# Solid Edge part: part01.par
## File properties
Author: Robert a Rhodes jr
Template: normal.par
Last saved by: Cadcim
Revision: 14
Application: Solid Edge
Accuracy: 0.99
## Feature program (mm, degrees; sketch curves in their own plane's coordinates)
sketch for "unnamed Protrusion 1" plane through (0, 0, 0) normal (0, 0, 1) x-axis (1, 0, 0)
  line (-63.0032, 49) -> (-56, -71)
  line (-56, -71) -> (56, -71)
  line (56, -71) -> (63.0032, 49)
  line (63.0032, 49) -> (0, 54)
  line (0, 54) -> (-63.0032, 49)
  dimension (linear) = 56
  dimension (linear) = 56
extrude "unnamed Protrusion 1" add finite 4 along +normal
fillet "Round_1" radius 15
sketch for "ExtrudedProtrusion_3" plane through (0, -8.5, 0) normal (0, 0, -1) x-axis (-1, 0, 0)
extrude "ExtrudedProtrusion_3" add finite 12 along -normal
pattern "unnamed Pattern 1" of "ExtrudedProtrusion_3"
pattern "unnamed Pattern 2"
sketch for "unnamed Protrusion 2" plane through (-1.0316, 2.3101, 4) normal (0, 0, 1) x-axis (-1, 0, 0)
extrude "unnamed Protrusion 2" add finite 5 along +normal
sketch for "Hole_22" plane through (40.9331, -54.9887, 12) normal (0, 0, 1) x-axis (1, 0, 0)
  hole centre (-0.4331, -0.0113) bore radius 4.5
hole "Hole_22" diameter 9 through  CounterBoreDepth = 5 mm
pattern "unnamed Pattern 3" of "Hole_22"
hole "unnamed Hole 1" through
hole "unnamed Hole 2" through
hole "unnamed Hole 3" through
sketch for "Hole_29" plane through (-1.0316, -6.1899, 9) normal (0, 0, 1) x-axis (1, 0, 0)
  hole centre (0, 0) bore radius 11
hole "Hole_29" diameter 22 through
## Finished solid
Body 1: solid body, 34 faces, 55 edges, 18 vertices.
  Faces by surface: cylinder 18, plane 16
  Edges by curve: circle 36, line 19
Bounding box of the edges (mm): 124.346 x 125.000 x 12.000, from (-62.1729, -71, 0) to (62.1729, 54, 12).
Cylindrical faces by radius (mm): R4.5 x4, R7.5 x4, R10.7006 x4, R11 x1, R15 x4, R20 x1
Planar faces by outward normal: +z 10, -y 1, -z 1, oblique 4
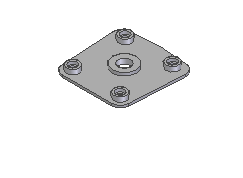
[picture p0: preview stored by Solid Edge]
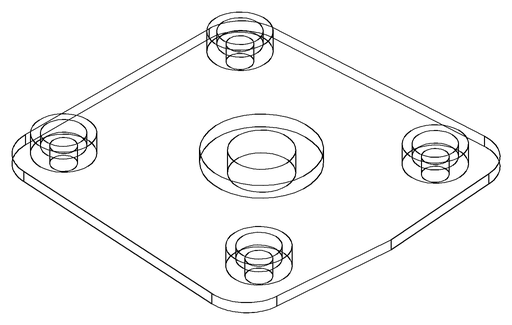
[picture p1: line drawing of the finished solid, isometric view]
